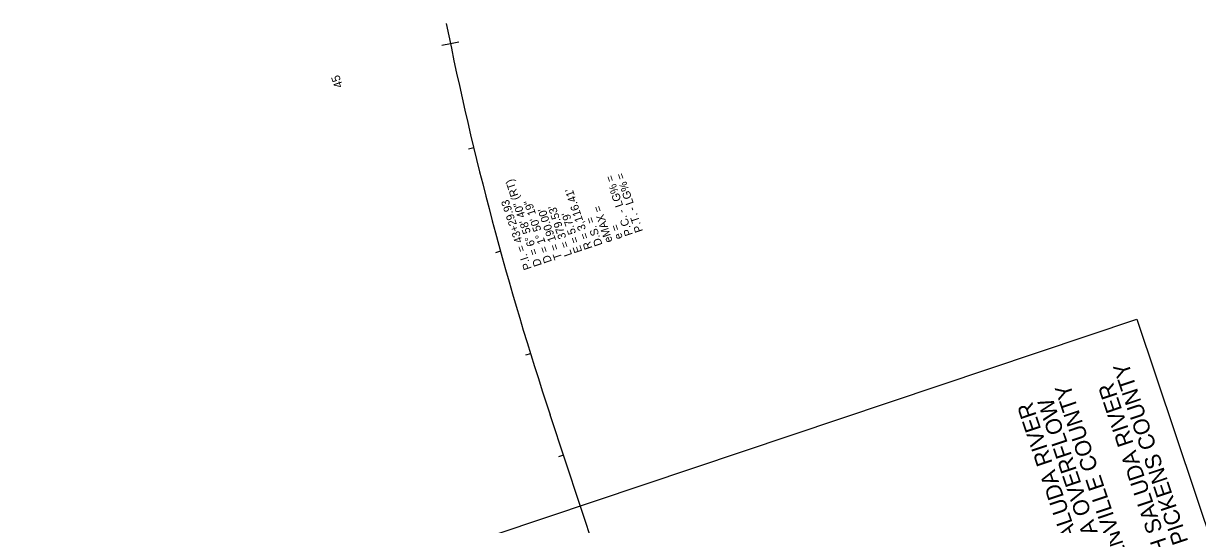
# Model space of a CAD drawing. Extents: x 1528853 to 1624411, y 1119753 to 1162242.
# Drawn here: x 1528853 to 1529953, y 1161081 to 1161550 of the extents above; entities that cross this region are included whole.
import ezdxf

# ---------------------------------------------------------------- set-up
doc = ezdxf.new("R2010")
doc.units = 0
for name, color, linetype in [('RD_HC_Cl', 7, 'Continuous'), ('RD_HC_Data', 7, 'Continuous'), ('RD_HC_Data_Tic', 7, 'Continuous'), ('RD_HC_TX_Sta50', 7, 'Continuous'), ('RD_SHT_ShtClip', 7, 'Continuous'), ('RD_SHT_TX', 7, 'Continuous')]:
    doc.layers.add(name, color=color, linetype=linetype)

msp = doc.modelspace()

# ---------------------------------------------------------------- linework, layer by layer
at = {"layer": 'RD_HC_Cl'}
msp.add_line((1529406, 1161003.2), (1529346.2, 1161183.5), dxfattribs=at)
msp.add_arc((1532304.3, 1162164.3), 3116.4, 191.3675, 198.3453, dxfattribs=at)
at = {"layer": 'RD_HC_Data_Tic'}
for p, q in [((1529260.7, 1161532.7), (1529252.9, 1161531)), ((1529252.9, 1161531), (1529245, 1161529.4)), ((1529274.8, 1161433.5), (1529269.9, 1161432.3)), ((1529299.8, 1161336.6), (1529295, 1161335.3)), ((1529327.9, 1161240.7), (1529323.1, 1161239.2)), ((1529358.8, 1161145.6), (1529354.1, 1161144))]:
    msp.add_line(p, q, dxfattribs=at)
at = {"layer": 'RD_SHT_ShtClip'}
for p, q in [((1528853, 1160923.1), (1529895.8, 1161273.1)), ((1529895.8, 1161273.1), (1530516.2, 1159424.4))]:
    msp.add_line(p, q, dxfattribs=at)

# ---------------------------------------------------------------- texts
at = {"layer": 'RD_HC_Data'}
for s, p in [('    = 6%%d 58\' 40" (RT)', (1529338.6, 1161323.8)), ('P.C. - LG% = ', (1529423.9, 1161352.4)), ('P.T. - LG% = ', (1529433.4, 1161355.6)), ("R = 3,116.41'", (1529386, 1161339.7)), ('P.I. = 43+29.93', (1529329.1, 1161320.6)), ('D = 1%%d 50\' 19"', (1529348.1, 1161327)), ('eMAX = ', (1529405, 1161346.1)), ("T = 190.00'", (1529357.6, 1161330.2)), ("L = 379.53'", (1529367, 1161333.3)), ("E = 5.79'", (1529376.5, 1161336.5)), ('D.S. = ', (1529395.5, 1161342.9)), ('e = ', (1529414.5, 1161349.2)), ('D', (1529338.6, 1161323.8))]:
    msp.add_text(s, height=7.5, rotation=108.5481, dxfattribs=at).set_placement(p)
at = {"layer": 'RD_HC_TX_Sta50'}
msp.add_text('45', height=8, rotation=108.568, dxfattribs=at).set_placement((1529152.3, 1161491.2))
at = {"layer": 'RD_SHT_TX'}
for s, p in [('PICKENS COUNTY', (1529944.3, 1161064.7)), ('S-26 OVER TRIBUTARY TO SOUTH SALUDA RIVER', (1530028.1, 1160753.9)), ('GREENVILLE COUNTY', (1529901.7, 1161008.6)), ('S-40 OVER SOUTH SALUDA RIVER', (1529903.7, 1160880.4)), ('S-40 OVER SOUTH SALUDA OVERFLOW', (1529939.9, 1160833.6))]:
    msp.add_text(s, height=15, rotation=108.5527, dxfattribs=at).set_placement(p)

doc.saveas('drawing.dxf')
